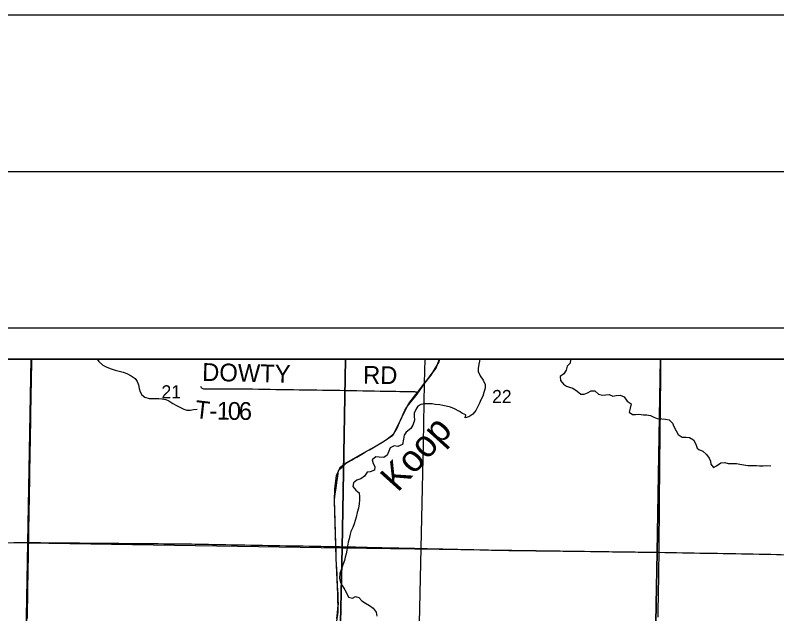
# Model space of a CAD drawing. Extents: x -11.1 to 34, y -3.9 to 22.
# Drawn here: x 3.372 to 5.806, y 20.086 to 22 of the extents above; entities that cross this region are included whole.
import ezdxf

# ---------------------------------------------------------------- set-up
doc = ezdxf.new("R2010")
doc.units = 0
for name, color, linetype in [('GM_X_Corporation', 7, 'Continuous'), ('GM_X_County_Road', 7, 'Continuous'), ('GM_X_Minor_River', 7, 'Continuous'), ('GM_X_Minor_River_Text', 7, 'Continuous'), ('GM_X_Rail_Line', 7, 'Continuous'), ('GM_X_Section_Text', 7, 'Continuous'), ('GM_X_State_Route', 7, 'Continuous'), ('GM_X_Township_Road', 7, 'Continuous'), ('GM_X_Township_Road_Text', 7, 'Continuous'), ('SH_Border', 7, 'Continuous'), ('SH_Cut_Line', 7, 'Continuous'), ('SH_Data', 7, 'Continuous')]:
    doc.layers.add(name, color=color, linetype=linetype)

msp = doc.modelspace()

# ---------------------------------------------------------------- linework, layer by layer
at = {"layer": 'GM_X_Corporation'}
for points in [[(8.9, 20.9), (2.1, 20.9), (2.1, 14.1), (7.332, 14.1)], [(7.452, 20.9), (2.1, 20.9), (2.1, 18.3243), (2.3663, 18.3195), (2.386, 18.3192), (3.3765, 18.301), (3.3885, 18.301), (4.3933, 18.2849), (4.8079, 18.2783), (5.3973, 18.2661), (6.2873, 18.2553), (6.3214, 18.2549), (6.5234, 18.2515), (7.399, 18.2383)]]:
    msp.add_lwpolyline(points, dxfattribs=at)
for points in [[(3.4231, 20.9), (2.4189, 20.9), (2.4116, 20.3267), (3.4122, 20.3123)], [(4.427, 20.9), (3.4231, 20.9), (3.4122, 20.3123), (4.4169, 20.2967)], [(5.4337, 20.9), (4.427, 20.9), (4.4169, 20.2967), (5.4232, 20.283)], [(6.4389, 20.9), (5.4337, 20.9), (5.4232, 20.283), (6.4249, 20.2637)], [(3.4122, 20.3123), (3.3936, 19.3072), (2.3914, 19.3197), (2.4116, 20.3267)], [(4.4169, 20.2967), (4.3941, 19.2891), (3.3936, 19.3072), (3.4122, 20.3123)], [(4.4169, 20.2967), (5.4232, 20.283), (5.4044, 19.2723), (4.3941, 19.2891)], [(5.4232, 20.283), (6.4249, 20.2637), (6.4054, 19.2568), (5.4044, 19.2723)]]:
    msp.add_lwpolyline(points, close=True, dxfattribs=at)
at = {"layer": 'GM_X_County_Road'}
msp.add_lwpolyline([(4.3996, 20.0704), (4.4017, 20.0889), (4.4033, 20.1034), (4.4049, 20.118), (4.4042, 20.1319), (4.4035, 20.1475), (4.4027, 20.163), (4.4023, 20.1725), (4.4017, 20.1844), (4.4012, 20.1963), (4.4004, 20.2124), (4.3996, 20.2285), (4.3989, 20.2447), (4.3981, 20.2608), (4.3976, 20.2794), (4.3972, 20.29), (4.3969, 20.3007), (4.3963, 20.3193), (4.3958, 20.3366), (4.3952, 20.3539), (4.3946, 20.3726), (4.3941, 20.3905), (4.3935, 20.4084), (4.3929, 20.427), (4.3925, 20.4389), (4.3921, 20.4507), (4.3947, 20.4692), (4.3973, 20.4877), (4.3999, 20.5061), (4.4025, 20.5246), (4.404, 20.5345), (4.4054, 20.5445), (4.4141, 20.5526), (4.4229, 20.5607), (4.43, 20.5673), (4.4461, 20.5767), (4.4549, 20.5819), (4.4637, 20.5871), (4.4798, 20.5966), (4.4915, 20.6035), (4.5033, 20.6104), (4.5036, 20.6106), (4.5197, 20.6201), (4.5357, 20.6296), (4.547, 20.6362), (4.5583, 20.6429), (4.5685, 20.6509), (4.5787, 20.659), (4.5827, 20.6636), (4.5863, 20.6684), (4.5896, 20.6736), (4.5926, 20.6789), (4.5951, 20.6844), (4.5972, 20.6901), (4.5986, 20.6939), (4.6001, 20.6975), (4.607, 20.7133), (4.614, 20.7291), (4.6183, 20.7377), (4.6229, 20.7461), (4.628, 20.7543), (4.6335, 20.7622), (4.6448, 20.7771), (4.652, 20.7866), (4.6573, 20.7935), (4.6707, 20.8106), (4.6804, 20.8233), (4.6902, 20.8361), (4.7015, 20.8509), (4.7094, 20.8612), (4.7172, 20.8715), (4.7236, 20.8891), (4.7275, 20.9)], dxfattribs=at)
at = {"layer": 'GM_X_Minor_River'}
for points in [[(3.6336, 20.9), (3.6386, 20.8922), (3.6524, 20.8805), (3.6621, 20.8756), (3.6749, 20.8704), (3.6915, 20.8646), (3.7044, 20.8616), (3.7165, 20.8582), (3.7286, 20.8545), (3.7428, 20.8469), (3.7552, 20.8386), (3.7614, 20.8289), (3.7656, 20.8182), (3.7684, 20.806), (3.7708, 20.7956), (3.7766, 20.7856), (3.7863, 20.7789), (3.7995, 20.7744), (3.8147, 20.774), (3.8307, 20.7747), (3.8406, 20.7733), (3.8527, 20.7707), (3.8629, 20.767), (3.876, 20.7587), (3.8868, 20.7519), (3.9003, 20.7451), (3.9105, 20.7403), (3.9207, 20.7373), (3.9313, 20.737), (3.9413, 20.7394), (3.9531, 20.7403)], [(4.8569, 20.9), (4.8559, 20.8937), (4.8537, 20.8839), (4.8514, 20.8699), (4.8512, 20.8604), (4.8573, 20.8466), (4.8676, 20.833), (4.8736, 20.8188), (4.8737, 20.8074), (4.8699, 20.7931), (4.8662, 20.7821), (4.8602, 20.7705), (4.8557, 20.7589), (4.8497, 20.7469), (4.8436, 20.7356), (4.8342, 20.7237), (4.8218, 20.7153), (4.8099, 20.7126), (4.8117, 20.7224), (4.8012, 20.7265), (4.7914, 20.7324), (4.776, 20.7408), (4.7625, 20.7461), (4.7496, 20.7495), (4.739, 20.7517), (4.7288, 20.7535), (4.714, 20.755), (4.7041, 20.7568), (4.6946, 20.7574), (4.6805, 20.7567), (4.6679, 20.7551), (4.6583, 20.7497), (4.6523, 20.7388), (4.6466, 20.7272), (4.6471, 20.7177), (4.648, 20.7051), (4.6426, 20.6893), (4.6362, 20.6788), (4.6214, 20.6671), (4.6151, 20.6573), (4.6125, 20.6441)], [(5.147, 20.9), (5.146, 20.8986), (5.1457, 20.8868), (5.1363, 20.8772), (5.1322, 20.8644), (5.125, 20.8531), (5.1137, 20.8447), (5.1145, 20.8318), (5.1238, 20.8205), (5.1339, 20.8138), (5.1437, 20.8101), (5.1542, 20.8068), (5.1673, 20.7973), (5.18, 20.7879), (5.1906, 20.7876), (5.2007, 20.7926), (5.2122, 20.7984), (5.2244, 20.7985), (5.2363, 20.7883), (5.2492, 20.7849), (5.2591, 20.7858), (5.2698, 20.787), (5.2822, 20.7817), (5.2929, 20.7837), (5.3055, 20.7853), (5.3175, 20.7793), (5.3275, 20.7657), (5.3402, 20.757), (5.3371, 20.743), (5.3345, 20.7306), (5.3442, 20.7235), (5.3537, 20.7232), (5.3648, 20.7237), (5.38, 20.7221), (5.3895, 20.7219), (5.402, 20.7197), (5.4133, 20.7148), (5.4238, 20.7107), (5.4379, 20.7092), (5.45, 20.7085), (5.4614, 20.7059), (5.4721, 20.695), (5.4772, 20.685), (5.4837, 20.6711), (5.4906, 20.6592), (5.5036, 20.6501), (5.5166, 20.6509), (5.5268, 20.6495), (5.54, 20.6423), (5.5472, 20.628), (5.5514, 20.615)], [(4.6125, 20.6441), (4.6093, 20.6276), (4.5948, 20.6211), (4.583, 20.6225), (4.5704, 20.6167), (4.566, 20.6054), (4.5608, 20.593), (4.5496, 20.5857), (4.5352, 20.5868), (4.5242, 20.5874), (4.5123, 20.5786), (4.5154, 20.5663), (4.5209, 20.5567), (4.5198, 20.5446), (4.5064, 20.5396), (4.4966, 20.5387), (4.4883, 20.526), (4.476, 20.5171), (4.4634, 20.5132), (4.4533, 20.5047), (4.4511, 20.4923), (4.4604, 20.4814), (4.4708, 20.4724), (4.4724, 20.4599), (4.4725, 20.45), (4.4715, 20.4371), (4.4693, 20.4239), (4.4652, 20.4095), (4.4614, 20.3952), (4.4578, 20.3846), (4.4552, 20.3733), (4.4508, 20.3616), (4.4448, 20.3485), (4.4415, 20.3356), (4.439, 20.3251), (4.4361, 20.3145), (4.4335, 20.3016), (4.4313, 20.2895), (4.4292, 20.277), (4.4267, 20.2669), (4.4238, 20.2563), (4.4193, 20.2423), (4.4132, 20.2258), (4.4095, 20.2145), (4.4084, 20.1997), (4.4112, 20.1859), (4.4163, 20.1759), (4.4258, 20.1621), (4.4301, 20.1525), (4.4367, 20.1394), (4.4495, 20.1361), (4.4591, 20.1408), (4.4696, 20.1379), (4.4796, 20.127), (4.4912, 20.1195), (4.5036, 20.1124), (4.5159, 20.1041), (4.5255, 20.0914), (4.5275, 20.0784)], [(5.5514, 20.615), (5.5561, 20.6115), (5.5696, 20.6062), (5.5811, 20.5953), (5.5895, 20.5837), (5.5938, 20.5741), (5.5947, 20.5646), (5.6036, 20.5541), (5.6132, 20.5588), (5.6267, 20.5683), (5.6392, 20.5691), (5.6502, 20.5669), (5.6661, 20.5669), (5.6767, 20.5666), (5.6873, 20.5644), (5.7009, 20.5618), (5.7137, 20.5603), (5.7411, 20.5604), (5.7509, 20.5594), (5.7619, 20.5591), (5.7733, 20.5599), (5.7866, 20.5592)]]:
    msp.add_lwpolyline(points, dxfattribs=at)
at = {"layer": 'GM_X_Rail_Line'}
for points in [[(4.8375, 14.1), (4.84, 14.2474), (4.8556, 15.259), (4.8714, 16.2666), (4.8783, 16.7081), (4.896, 17.8593), (4.8941, 17.9315), (4.8895, 17.9844), (4.8767, 18.0419), (4.6837, 18.6752), (4.6608, 18.751), (4.6471, 18.7984), (4.6397, 18.855), (4.6467, 19.2877), (4.6769, 20.631), (4.6804, 20.8229), (4.6818, 20.9)], [(4.7283, 20.9), (4.7254, 20.8919), (4.6999, 20.8492), (4.6802, 20.8234)], [(4.6802, 20.8234), (4.6549, 20.7884), (4.6249, 20.7501), (4.5791, 20.6563), (4.5461, 20.6338), (4.4803, 20.5968), (4.4302, 20.5688), (4.4098, 20.5528), (4.3973, 20.5266), (4.3918, 20.4856), (4.3909, 20.4464), (4.3968, 20.2646), (4.4015, 20.1476), (4.4029, 20.091), (4.3921, 20.0182), (4.3791, 19.887), (4.2803, 18.9936), (4.2822, 18.9589), (4.3352, 18.597), (4.3921, 18.288), (4.3976, 18.2496), (4.3933, 17.8598)]]:
    msp.add_lwpolyline(points, dxfattribs=at)
at = {"layer": 'GM_X_State_Route'}
for points in [[(5.4264, 20.0749), (5.4268, 20.0935), (5.4271, 20.1122), (5.4274, 20.1308), (5.4277, 20.1495), (5.428, 20.1681), (5.4283, 20.1868), (5.4286, 20.2054), (5.4289, 20.224), (5.4292, 20.2427), (5.4295, 20.2613), (5.4296, 20.2719), (5.4298, 20.2824), (5.4299, 20.3011), (5.4301, 20.3197), (5.4302, 20.3383), (5.4303, 20.357), (5.4304, 20.3756), (5.4305, 20.3943), (5.4307, 20.4129), (5.4307, 20.4236), (5.4308, 20.4343), (5.431, 20.4529), (5.4312, 20.4716), (5.4314, 20.4902), (5.4316, 20.5088), (5.4318, 20.5275), (5.432, 20.5461), (5.4322, 20.5648), (5.4323, 20.5834), (5.4325, 20.6021), (5.4327, 20.6207), (5.4329, 20.6393), (5.4331, 20.658), (5.4333, 20.6766), (5.4335, 20.6953), (5.4337, 20.7139), (5.4339, 20.7325), (5.4341, 20.7512), (5.4343, 20.7698), (5.4345, 20.7885), (5.4347, 20.8071), (5.4349, 20.8257), (5.4351, 20.8444), (5.4353, 20.863), (5.4355, 20.8817), (5.4356, 20.9)], [(3.3674, 20.3141), (3.3861, 20.314), (3.4005, 20.3138), (3.415, 20.3137), (3.4336, 20.3135), (3.4522, 20.3134), (3.4709, 20.3132), (3.4895, 20.313), (3.5082, 20.3129), (3.5243, 20.3127), (3.5404, 20.3126), (3.559, 20.3124), (3.5777, 20.3123), (3.5963, 20.3121), (3.615, 20.3119), (3.6336, 20.3118), (3.6497, 20.3116), (3.6658, 20.3115), (3.6845, 20.3113), (3.7031, 20.3112), (3.7218, 20.311), (3.7404, 20.3108), (3.759, 20.3107), (3.7752, 20.3105), (3.7913, 20.3104), (3.8099, 20.3102), (3.8285, 20.3101), (3.8472, 20.3099), (3.8606, 20.3098), (3.874, 20.3097), (3.8927, 20.3095), (3.9047, 20.3094), (3.9167, 20.3093), (3.9353, 20.309), (3.9473, 20.3088), (3.9593, 20.3085), (3.9779, 20.3082), (3.9899, 20.308), (4.0019, 20.3078), (4.0205, 20.3074), (4.0325, 20.3072), (4.0445, 20.307), (4.0631, 20.3067), (4.0751, 20.3065), (4.0871, 20.3062), (4.1058, 20.3059), (4.1244, 20.3056), (4.1431, 20.3052), (4.1617, 20.3049), (4.1804, 20.3046), (4.199, 20.3042), (4.2176, 20.3039), (4.2363, 20.3036), (4.2549, 20.3032), (4.2736, 20.3029), (4.2922, 20.3026), (4.3108, 20.3022), (4.3244, 20.302), (4.338, 20.3018), (4.3483, 20.3016), (4.3586, 20.3014), (4.3773, 20.301), (4.3871, 20.3009), (4.3969, 20.3007), (4.4078, 20.3005), (4.4188, 20.3003), (4.4296, 20.3001), (4.4404, 20.2998), (4.459, 20.2994), (4.4776, 20.299), (4.4963, 20.2986), (4.5149, 20.2981), (4.5293, 20.2978), (4.5438, 20.2975), (4.5624, 20.2971), (4.5754, 20.2968), (4.5884, 20.2965), (4.5979, 20.2963), (4.6165, 20.2958), (4.6352, 20.2954), (4.6478, 20.2951), (4.6604, 20.2949), (4.6699, 20.2946), (4.6793, 20.2944), (4.683, 20.2943), (4.6887, 20.2942), (4.7074, 20.2938), (4.726, 20.2934), (4.7383, 20.2931), (4.7506, 20.2928), (4.7638, 20.2925), (4.7793, 20.2922), (4.7867, 20.292), (4.7961, 20.2918), (4.814, 20.2914), (4.8319, 20.291), (4.8377, 20.2909), (4.8563, 20.2904), (4.8678, 20.2902), (4.8793, 20.2899), (4.8848, 20.2898), (4.8943, 20.2896), (4.9076, 20.2893), (4.9209, 20.289), (4.9351, 20.2888), (4.9493, 20.2886), (4.9679, 20.2884), (4.9862, 20.2881), (5.0044, 20.2879), (5.023, 20.2877), (5.0358, 20.2875), (5.0487, 20.2873), (5.0673, 20.2871), (5.086, 20.2869), (5.1046, 20.2866), (5.1232, 20.2864), (5.1419, 20.2861), (5.1574, 20.2859), (5.1729, 20.2857), (5.1916, 20.2855), (5.2102, 20.2853), (5.2288, 20.285), (5.2475, 20.2848), (5.2661, 20.2845), (5.2811, 20.2843), (5.2962, 20.2842), (5.3107, 20.284), (5.3253, 20.2838), (5.344, 20.2835), (5.3536, 20.2834), (5.3632, 20.2833), (5.3774, 20.2831), (5.3916, 20.2829), (5.4101, 20.2827), (5.4298, 20.2824), (5.4484, 20.2821), (5.4671, 20.2818), (5.4857, 20.2814), (5.5044, 20.2811), (5.523, 20.2808), (5.5416, 20.2804), (5.5603, 20.2801), (5.5789, 20.2798), (5.5976, 20.2794), (5.6162, 20.2791), (5.6349, 20.2788), (5.6459, 20.2786), (5.6569, 20.2784), (5.6747, 20.2781), (5.6934, 20.2778), (5.712, 20.2774), (5.7307, 20.2771), (5.7493, 20.2768), (5.7679, 20.2764), (5.7866, 20.2761), (5.8052, 20.2758), (5.8193, 20.2755)]]:
    msp.add_lwpolyline(points, dxfattribs=at)
at = {"layer": 'GM_X_Township_Road'}
for points in [[(3.415, 20.3137), (3.4153, 20.3323), (3.4156, 20.351), (3.4159, 20.3696), (3.4162, 20.3882), (3.4166, 20.4069), (3.4169, 20.4255), (3.4172, 20.4442), (3.4175, 20.4628), (3.4178, 20.4815), (3.4182, 20.5001), (3.4185, 20.5187), (3.4188, 20.5374), (3.4191, 20.556), (3.4194, 20.5747), (3.4198, 20.5933), (3.4201, 20.6119), (3.4204, 20.6306), (3.4207, 20.6492), (3.421, 20.6679), (3.4214, 20.6865), (3.4217, 20.7051), (3.422, 20.7238), (3.4223, 20.7424), (3.4226, 20.7611), (3.423, 20.7797), (3.4233, 20.7982), (3.4236, 20.8167), (3.4239, 20.8354), (3.4242, 20.854), (3.4246, 20.8727), (3.4249, 20.8913), (3.425, 20.9)], [(3.964, 20.8137), (3.9647, 20.8118), (3.9658, 20.8097), (3.967, 20.8083), (3.9689, 20.807), (3.9714, 20.8061), (3.9741, 20.8056), (3.9769, 20.8055), (3.9933, 20.8056), (4.0403, 20.8053), (4.0785, 20.8051), (4.1116, 20.805), (4.1302, 20.8047), (4.1489, 20.8044), (4.1675, 20.8041), (4.1862, 20.8038), (4.2048, 20.8035), (4.2235, 20.8033), (4.2421, 20.803), (4.2607, 20.8027), (4.2794, 20.8024), (4.298, 20.8021), (4.3167, 20.8018), (4.3353, 20.8016), (4.3539, 20.8013), (4.3726, 20.801), (4.3912, 20.8007), (4.409, 20.8004), (4.4267, 20.8002), (4.4454, 20.7999), (4.464, 20.7995), (4.4826, 20.7992), (4.5013, 20.7989), (4.5199, 20.7986), (4.5386, 20.7982), (4.5572, 20.7979), (4.5758, 20.7976), (4.5885, 20.7974), (4.6012, 20.7971), (4.6132, 20.7969), (4.6252, 20.7967), (4.6422, 20.7964), (4.6474, 20.7962), (4.6502, 20.796), (4.6528, 20.7955), (4.6573, 20.7935)], [(3.4108, 20.0708), (3.4111, 20.0895), (3.4114, 20.1081), (3.4117, 20.1268), (3.4121, 20.1454), (3.4124, 20.164), (3.4127, 20.1827), (3.413, 20.2013), (3.4134, 20.22), (3.4137, 20.2386), (3.414, 20.2572), (3.4143, 20.2759), (3.4146, 20.2945), (3.4148, 20.3041), (3.415, 20.3137)]]:
    msp.add_lwpolyline(points, dxfattribs=at)
at = {"layer": 'SH_Border'}
msp.add_lwpolyline([(1.5, 21.5), (33.5, 21.5), (33.5, 0.5), (1.5, 0.5)], close=True, dxfattribs=at)
at = {"layer": 'SH_Cut_Line'}
msp.add_lwpolyline([(0, 0), (34, 0), (34, 22), (0, 22)], close=True, dxfattribs=at)
at = {"layer": 'SH_Data'}
for p, q in [((2, 21), (9, 21)), ((2.1, 20.9), (8.9, 20.9))]:
    msp.add_line(p, q, dxfattribs=at)

# ---------------------------------------------------------------- texts
at = {"layer": 'GM_X_Minor_River_Text'}
msp.add_text('Koop', height=0.08523, rotation=48.0199, dxfattribs=at).set_placement((4.5945, 20.4719))
at = {"layer": 'GM_X_Section_Text'}
for s, p in [('21', (3.8394, 20.7747)), ('22', (4.896, 20.7597))]:
    msp.add_text(s, height=0.04186, rotation=0, dxfattribs=at).set_placement(p)
at = {"layer": 'GM_X_Township_Road_Text'}
for s, height, rotation, p in [('DOWTY', 0.05682, 358.7057, (3.9688, 20.8308)), ('RD', 0.05682, 359.0181, (4.4831, 20.8217)), ('T', 0.0568, 353.4932, (3.944, 20.7125)), ('1', 0.0568, 359.2356, (4.0158, 20.7067)), ('0', 0.0568, 359.5966, (4.0512, 20.7062)), ('6', 0.0568, 359.7076, (4.0863, 20.706)), ('-', 0.0568, 358.605, (3.9918, 20.7073))]:
    msp.add_text(s, height=height, rotation=rotation, dxfattribs=at).set_placement(p)

doc.saveas('drawing.dxf')
